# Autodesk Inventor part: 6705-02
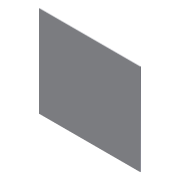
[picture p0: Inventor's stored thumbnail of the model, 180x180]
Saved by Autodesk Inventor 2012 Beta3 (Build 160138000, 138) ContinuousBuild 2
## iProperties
Created: 2011-02
Part Number: 6705-02
Material: Default
Document SubType Name: Modeling
Designer: Beta-8540w
Density: 1 g/cm^3
Author: Beta-8540w
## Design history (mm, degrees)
sketch "Sketch1"
  geometry: L1 (-225.425, 203.2)-(225.425, 203.2); L2 (225.425, 203.2)-(225.425, -203.2); L3 (225.425, -203.2)-(-225.425, -203.2); L4 (-225.425, -203.2)-(-225.425, 203.2); 3 further points
  constraints: 8 end point, 2 midpoint, 2 parallel, 1 horizontal, 1 horizontal alignment, 1 perpendicular, 1 vertical alignment
  dimensions: "bottom_width" = 450.85 distance of L2.end L3.end; "drawer_depth" = 406.4 distance of L1.end L2.end
extrude "Extrusion1" new body sketch "Sketch1" taper "d3" = 0 deg; distance "bottom_thickness" = 3.302
body "Solid1"
